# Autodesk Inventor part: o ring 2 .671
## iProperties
Created: 2007-11
Part Number: o ring 2 .671
Document SubType Name: Modeling
Designer: lwoods
Density: 1 g/cm^3
Author: lwoods
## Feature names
1. Revolution1
